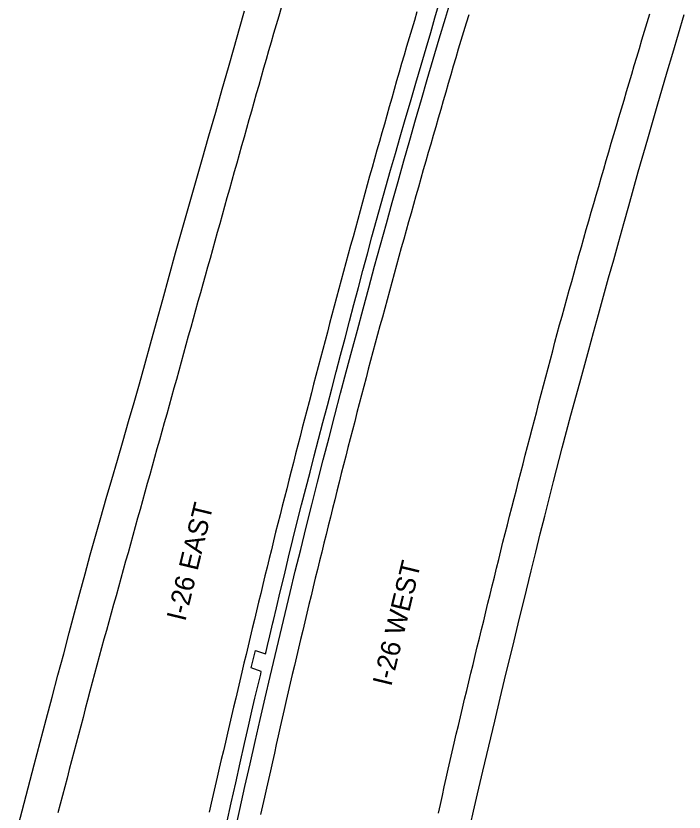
# Model space of a CAD drawing. Extents: x 1948091 to 1975253, y 787267 to 823306.
# Drawn here: x 1966417.5 to 1966603.2, y 791600.8 to 791822.2 of the extents above; entities that cross this region are included whole.
import ezdxf

# ---------------------------------------------------------------- set-up
doc = ezdxf.new("R2010")
doc.units = 0
for name, color, linetype in [('RD_EX_Pavement_Markings', 7, 'Continuous'), ('RD_EX_Road', 7, 'Continuous'), ('RD_TX_RoadID', 7, 'Continuous')]:
    doc.layers.add(name, color=color, linetype=linetype)

msp = doc.modelspace()

# ---------------------------------------------------------------- linework, layer by layer
at = {"layer": 'RD_EX_Pavement_Markings'}
for points in [[(1966491.27, 791824.47), (1966490.56, 791822.08), (1966489.84, 791819.68), (1966489.13, 791817.29), (1966488.42, 791814.89), (1966487.72, 791812.5), (1966487.04, 791810.09), (1966486.36, 791807.69), (1966485.68, 791805.28), (1966485, 791802.88), (1966484.32, 791800.48), (1966483.64, 791798.07), (1966482.96, 791795.67), (1966482.28, 791793.26), (1966481.6, 791790.86), (1966480.92, 791788.46), (1966480.24, 791786.05), (1966479.56, 791783.65), (1966478.87, 791781.24), (1966478.19, 791778.84), (1966477.51, 791776.44), (1966476.83, 791774.03), (1966476.16, 791771.63), (1966475.49, 791769.22), (1966474.82, 791766.81), (1966474.15, 791764.4), (1966473.48, 791762), (1966472.81, 791759.59), (1966472.13, 791757.18), (1966471.46, 791754.78), (1966470.79, 791752.37), (1966470.12, 791749.96), (1966469.45, 791747.56), (1966468.78, 791745.15), (1966468.11, 791742.74), (1966467.44, 791740.34), (1966466.76, 791737.93), (1966466.09, 791735.52), (1966465.42, 791733.12), (1966464.76, 791730.71), (1966464.1, 791728.3), (1966463.43, 791725.89), (1966462.77, 791723.48), (1966462.11, 791721.07), (1966461.44, 791718.67), (1966460.77, 791716.26), (1966460.1, 791713.85), (1966459.42, 791711.45), (1966458.75, 791709.04), (1966458.07, 791706.64), (1966457.4, 791704.23), (1966456.72, 791701.83), (1966456.05, 791699.42), (1966455.38, 791697.01), (1966454.7, 791694.61), (1966454.03, 791692.2), (1966453.35, 791689.8), (1966452.68, 791687.39), (1966452.01, 791684.98), (1966451.34, 791682.58), (1966450.67, 791680.17), (1966450.01, 791677.76), (1966449.34, 791675.35), (1966448.67, 791672.94), (1966448, 791670.54), (1966447.33, 791668.13), (1966446.66, 791665.72), (1966446, 791663.31), (1966445.33, 791660.91), (1966444.66, 791658.5), (1966443.99, 791656.09), (1966443.32, 791653.68), (1966442.65, 791651.28), (1966441.99, 791648.87), (1966441.32, 791646.46), (1966440.65, 791644.05), (1966439.98, 791641.65), (1966439.34, 791639.23), (1966438.7, 791636.82), (1966438.07, 791634.4), (1966437.43, 791631.98), (1966436.8, 791629.57), (1966436.16, 791627.15), (1966435.52, 791624.74), (1966434.89, 791622.32), (1966434.25, 791619.91), (1966433.62, 791617.49), (1966432.98, 791615.07), (1966432.34, 791612.66), (1966431.71, 791610.24), (1966431.07, 791607.83), (1966430.44, 791605.41), (1966429.8, 791602.99), (1966429.18, 791600.57)], [(1966528.97, 791823.28), (1966528.25, 791820.89), (1966527.54, 791818.49), (1966526.83, 791816.1), (1966526.11, 791813.7), (1966525.4, 791811.31), (1966524.69, 791808.91), (1966523.99, 791806.52), (1966523.31, 791804.11), (1966522.63, 791801.71), (1966521.95, 791799.3), (1966521.27, 791796.9), (1966520.59, 791794.49), (1966519.91, 791792.09), (1966519.23, 791789.69), (1966518.55, 791787.28), (1966517.87, 791784.88), (1966517.19, 791782.47), (1966516.51, 791780.07), (1966515.83, 791777.66), (1966515.15, 791775.26), (1966514.48, 791772.85), (1966513.83, 791770.44), (1966513.17, 791768.03), (1966512.52, 791765.62), (1966511.86, 791763.21), (1966511.21, 791760.79), (1966510.55, 791758.38), (1966509.89, 791755.97), (1966509.24, 791753.56), (1966508.58, 791751.15), (1966507.93, 791748.74), (1966507.27, 791746.33), (1966506.62, 791743.92), (1966505.99, 791741.5), (1966505.35, 791739.08), (1966504.71, 791736.67), (1966504.08, 791734.25), (1966503.44, 791731.83), (1966502.81, 791729.42), (1966502.17, 791727), (1966501.54, 791724.58), (1966500.9, 791722.17), (1966500.26, 791719.75), (1966499.63, 791717.34), (1966498.99, 791714.92), (1966498.36, 791712.5), (1966497.72, 791710.09), (1966497.11, 791707.66), (1966496.49, 791705.24), (1966495.87, 791702.82), (1966495.25, 791700.4), (1966494.63, 791697.98), (1966494.02, 791695.56), (1966493.4, 791693.14), (1966492.78, 791690.72), (1966492.16, 791688.3), (1966491.54, 791685.88), (1966490.92, 791683.46), (1966490.31, 791681.04), (1966489.69, 791678.61), (1966489.1, 791676.19), (1966488.51, 791673.76), (1966487.92, 791671.33), (1966487.33, 791668.9), (1966486.74, 791666.47), (1966486.15, 791664.05), (1966485.57, 791661.62), (1966484.98, 791659.19), (1966484.39, 791656.76), (1966483.8, 791654.33), (1966483.21, 791651.9), (1966482.62, 791649.48), (1966482.04, 791647.05), (1966481.47, 791644.61), (1966480.9, 791642.18), (1966480.32, 791639.75), (1966479.75, 791637.32), (1966479.18, 791634.89), (1966478.6, 791632.46), (1966478.03, 791630.02), (1966477.46, 791627.59), (1966476.88, 791625.16), (1966476.31, 791622.73), (1966475.74, 791620.3), (1966475.17, 791617.86), (1966474.6, 791615.43), (1966474.04, 791613), (1966473.48, 791610.56), (1966472.93, 791608.12), (1966472.37, 791605.69), (1966471.81, 791603.25), (1966471.26, 791600.82)], [(1966543.39, 791822.52), (1966542.66, 791820.14), (1966541.93, 791817.75), (1966541.2, 791815.36), (1966540.46, 791812.97), (1966539.75, 791810.57), (1966539.06, 791808.17), (1966538.36, 791805.77), (1966537.67, 791803.37), (1966536.97, 791800.97), (1966536.27, 791798.57), (1966535.58, 791796.17), (1966534.88, 791793.77), (1966534.19, 791791.37), (1966533.49, 791788.97), (1966532.79, 791786.57), (1966532.1, 791784.17), (1966531.42, 791781.77), (1966530.74, 791779.36), (1966530.06, 791776.96), (1966529.38, 791774.55), (1966528.7, 791772.15), (1966528.02, 791769.75), (1966527.34, 791767.34), (1966526.66, 791764.94), (1966525.98, 791762.53), (1966525.3, 791760.13), (1966524.63, 791757.72), (1966523.95, 791755.32), (1966523.3, 791752.91), (1966522.64, 791750.5), (1966521.98, 791748.08), (1966521.33, 791745.67), (1966520.67, 791743.26), (1966520.01, 791740.85), (1966519.36, 791738.44), (1966518.7, 791736.03), (1966518.04, 791733.62), (1966517.39, 791731.21), (1966516.73, 791728.8), (1966516.08, 791726.39), (1966515.45, 791723.97), (1966514.82, 791721.55), (1966514.2, 791719.13), (1966513.57, 791716.71), (1966512.94, 791714.29), (1966512.31, 791711.88), (1966511.69, 791709.46), (1966511.06, 791707.04), (1966510.43, 791704.62), (1966509.8, 791702.2), (1966509.18, 791699.78), (1966508.55, 791697.37), (1966507.94, 791694.94), (1966507.33, 791692.52), (1966506.73, 791690.09), (1966506.12, 791687.67), (1966505.52, 791685.24), (1966504.92, 791682.82), (1966504.31, 791680.4), (1966503.71, 791677.97), (1966503.1, 791675.55), (1966502.5, 791673.12), (1966501.89, 791670.7), (1966501.29, 791668.27), (1966500.7, 791665.85), (1966500.12, 791663.42), (1966499.54, 791660.98), (1966498.96, 791658.55), (1966498.38, 791656.12), (1966497.8, 791653.69), (1966497.23, 791651.26), (1966496.65, 791648.83), (1966496.07, 791646.4), (1966495.49, 791643.97), (1966494.91, 791641.54), (1966494.33, 791639.11), (1966493.75, 791636.68), (1966493.2, 791634.24), (1966492.65, 791631.81), (1966492.09, 791629.37), (1966491.54, 791626.93), (1966490.99, 791624.5), (1966490.44, 791622.06), (1966489.89, 791619.62), (1966489.34, 791617.19), (1966488.78, 791614.75), (1966488.23, 791612.31), (1966487.68, 791609.87), (1966487.13, 791607.44), (1966486.59, 791605), (1966486.05, 791602.56), (1966485.52, 791600.12)], [(1966534.98, 791600.51), (1966535.51, 791602.95), (1966536.04, 791605.39), (1966536.57, 791607.83), (1966537.1, 791610.27), (1966537.63, 791612.72), (1966538.17, 791615.16), (1966538.75, 791617.59), (1966539.32, 791620.02), (1966539.9, 791622.45), (1966540.48, 791624.88), (1966541.06, 791627.31), (1966541.64, 791629.74), (1966542.22, 791632.17), (1966542.8, 791634.6), (1966543.38, 791637.03), (1966543.97, 791639.46), (1966544.56, 791641.89), (1966545.16, 791644.32), (1966545.75, 791646.74), (1966546.34, 791649.17), (1966546.93, 791651.6), (1966547.52, 791654.03), (1966548.11, 791656.45), (1966548.71, 791658.88), (1966549.31, 791661.31), (1966549.9, 791663.73), (1966550.5, 791666.16), (1966551.1, 791668.59), (1966551.7, 791671.01), (1966552.29, 791673.44), (1966552.89, 791675.87), (1966553.49, 791678.29), (1966554.1, 791680.71), (1966554.73, 791683.13), (1966555.35, 791685.55), (1966555.97, 791687.97), (1966556.6, 791690.39), (1966557.22, 791692.81), (1966557.84, 791695.23), (1966558.47, 791697.65), (1966559.09, 791700.07), (1966559.71, 791702.49), (1966560.34, 791704.91), (1966560.98, 791707.33), (1966561.61, 791709.74), (1966562.25, 791712.16), (1966562.88, 791714.58), (1966563.52, 791716.99), (1966564.15, 791719.41), (1966564.79, 791721.83), (1966565.42, 791724.24), (1966566.06, 791726.66), (1966566.7, 791729.08), (1966567.33, 791731.49), (1966567.97, 791733.91), (1966568.64, 791736.32), (1966569.31, 791738.72), (1966569.98, 791741.13), (1966570.65, 791743.54), (1966571.32, 791745.94), (1966571.99, 791748.35), (1966572.66, 791750.76), (1966573.33, 791753.17), (1966574, 791755.57), (1966574.67, 791757.98), (1966575.34, 791760.39), (1966576.02, 791762.79), (1966576.72, 791765.19), (1966577.42, 791767.59), (1966578.11, 791769.99), (1966578.81, 791772.39), (1966579.51, 791774.79), (1966580.21, 791777.19), (1966580.91, 791779.59), (1966581.6, 791781.99), (1966582.3, 791784.39), (1966583, 791786.79), (1966583.7, 791789.19), (1966584.4, 791791.59), (1966585.11, 791793.98), (1966585.82, 791796.38), (1966586.53, 791798.77), (1966587.24, 791801.17), (1966587.95, 791803.56), (1966588.66, 791805.96), (1966589.37, 791808.36), (1966590.08, 791810.75), (1966590.79, 791813.15), (1966591.49, 791815.54), (1966592.21, 791817.94), (1966592.94, 791820.33), (1966593.66, 791822.72)]]:
    msp.add_lwpolyline(points, dxfattribs=at)
at = {"layer": 'RD_EX_Road'}
for points in [[(1966478.35, 791595.19), (1966479.75, 791601.53), (1966481.18, 791607.91), (1966482.61, 791614.26), (1966484.02, 791620.48), (1966485.42, 791626.59), (1966486.81, 791632.58), (1966488.19, 791638.5), (1966489.57, 791644.37), (1966490.94, 791650.21), (1966492.32, 791656.01), (1966493.72, 791661.84), (1966495.17, 791667.79), (1966496.66, 791673.86), (1966498.19, 791680.03), (1966499.75, 791686.27), (1966501.34, 791692.51), (1966502.94, 791698.75), (1966504.56, 791704.99), (1966506.17, 791711.18), (1966507.77, 791717.25), (1966509.34, 791723.2), (1966510.9, 791729.04), (1966512.45, 791734.84), (1966514.02, 791740.7), (1966515.61, 791746.62), (1966517.22, 791752.58), (1966518.84, 791758.55), (1966520.47, 791764.47), (1966522.09, 791770.33), (1966523.72, 791776.15), (1966525.34, 791781.92), (1966526.97, 791787.63), (1966528.59, 791793.31), (1966530.21, 791798.93), (1966531.85, 791804.54), (1966533.5, 791810.18), (1966535.17, 791815.84), (1966536.87, 791821.52), (1966538.58, 791827.24)], [(1966476.12, 791597.81), (1966477.34, 791603.35), (1966478.59, 791608.93), (1966479.84, 791614.55), (1966481.05, 791619.9), (1966482.14, 791624.67), (1966483.1, 791628.86), (1966483.95, 791632.47), (1966484.65, 791635.42), (1966485.18, 791637.65), (1966485.54, 791639.15), (1966485.72, 791639.93), (1966482.91, 791640.96), (1966484.14, 791645.71), (1966486.85, 791644.79), (1966487.02, 791645.48), (1966487.42, 791647.15), (1966488.05, 791649.79), (1966488.92, 791653.41), (1966489.08, 791654.07), (1966489.93, 791657.63), (1966491, 791662.08), (1966492.13, 791666.77), (1966493.31, 791671.68), (1966494.52, 791676.65), (1966495.72, 791681.49), (1966496.9, 791686.2), (1966498.07, 791690.78), (1966499.25, 791695.32), (1966500.43, 791699.89), (1966501.63, 791704.51), (1966502.85, 791709.16), (1966504.07, 791713.84), (1966505.29, 791718.52), (1966506.52, 791723.21), (1966507.75, 791727.9), (1966508.98, 791732.6), (1966510.22, 791737.29), (1966511.46, 791741.99), (1966512.71, 791746.68), (1966513.95, 791751.37), (1966515.21, 791756.06), (1966516.48, 791760.73), (1966517.75, 791765.4), (1966519.04, 791770.05), (1966520.34, 791774.69), (1966521.65, 791779.3), (1966522.98, 791783.89), (1966524.33, 791788.55), (1966525.73, 791793.37), (1966527.18, 791798.34), (1966528.67, 791803.46), (1966530.13, 791808.5), (1966531.51, 791813.2), (1966532.79, 791817.57), (1966533.98, 791821.61), (1966535, 791825.05)], [(1966417.51, 791594.53), (1966419.24, 791601.14), (1966420.93, 791607.59), (1966422.59, 791613.95), (1966424.25, 791620.26), (1966425.91, 791626.54), (1966427.57, 791632.77), (1966429.2, 791638.9), (1966430.79, 791644.84), (1966432.32, 791650.61), (1966433.81, 791656.2), (1966435.27, 791661.66), (1966436.72, 791667.03), (1966438.18, 791672.33), (1966439.63, 791677.55), (1966441.09, 791682.75), (1966442.59, 791688.02), (1966444.13, 791693.33), (1966445.71, 791698.71), (1966447.29, 791704.09), (1966448.83, 791709.42), (1966450.34, 791714.7), (1966451.83, 791719.93), (1966453.33, 791725.3), (1966454.91, 791730.99), (1966456.58, 791737), (1966458.32, 791743.34), (1966460.11, 791749.83), (1966461.91, 791756.32), (1966463.72, 791762.8), (1966465.55, 791769.27), (1966467.39, 791775.76), (1966469.25, 791782.28), (1966471.13, 791788.83), (1966473.03, 791795.41), (1966474.87, 791801.82), (1966476.59, 791807.82), (1966478.18, 791813.43), (1966479.65, 791818.64), (1966481.07, 791823.63)], [(1966543.83, 791597.35), (1966544.67, 791601.11), (1966545.82, 791605.93), (1966547.32, 791612.17), (1966548.99, 791619.12), (1966550.63, 791626.12), (1966552.12, 791632.49), (1966553.35, 791637.57), (1966554.46, 791642.1), (1966555.58, 791646.81), (1966557.11, 791653.15), (1966559.4, 791662.53), (1966560.72, 791667.9), (1966562.01, 791673.13), (1966563.26, 791678.21), (1966564.48, 791683.14), (1966566.89, 791692.73), (1966569.34, 791702.06), (1966571.79, 791711.19), (1966574.23, 791720.16), (1966576.76, 791729.36), (1966578.09, 791734.2), (1966579.47, 791739.18), (1966580.87, 791744.25), (1966582.26, 791749.33), (1966583.66, 791754.4), (1966585.06, 791759.48), (1966586.45, 791764.5), (1966587.82, 791769.4), (1966590.49, 791778.82), (1966593.12, 791787.97), (1966595.75, 791797.09), (1966598.54, 791806.68), (1966600.05, 791811.84), (1966601.63, 791817.23), (1966603.22, 791822.59)]]:
    msp.add_lwpolyline(points, dxfattribs=at)

# ---------------------------------------------------------------- texts
at = {"layer": 'RD_TX_RoadID'}
for s, p in [('I-26 EAST', (1966464.57, 791653.65)), ('I-26 WEST', (1966521.82, 791635.56))]:
    msp.add_text(s, height=5.4, rotation=76.4207, dxfattribs=at).set_placement(p)

doc.saveas('drawing.dxf')
